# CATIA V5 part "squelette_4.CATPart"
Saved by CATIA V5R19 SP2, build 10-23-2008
Part number: squelette_4
Publications: "Point.1", "Point.2", "Point.3", "Droite.1", "Droite.2", "Droite.3"
Bounding box of the stored display mesh (mm): x -10 to 10, y -16 to 16, z -3 to 3
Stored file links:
  M:\EU_thinkMotion\IAO_2010\iao\IAO_MMS_Groupe2\IAO_MMS_Groupe2\sdubois\sdubois\sdubois\IAO_mecanisme\squelette_4.CATPart
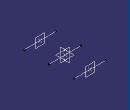
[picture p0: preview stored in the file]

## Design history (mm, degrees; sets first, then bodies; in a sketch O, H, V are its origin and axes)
Set1
  Point1: (0, 0, 0)
  Point2: (0, 16, 0)
  Point3: (0, -16, 0)
  Line1: type PtDir, RefPoint Point3, Direction yz-plane, Start -10, End 10
  Line2: type PtDir, RefPoint Point1, Direction yz-plane, Start -10, End 10
  Line3: type PtDir, RefPoint Point2, Direction yz-plane, Start -10, End 10
  Plane1: type OffsetPt, RefPlane zx-plane, RefPoint Point3
  Plane2: type OffsetPt, RefPlane zx-plane, RefPoint Point2
  Point4: (0, 0, 3)
  Point5: (0, 0, -3)
Body1 (main body)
